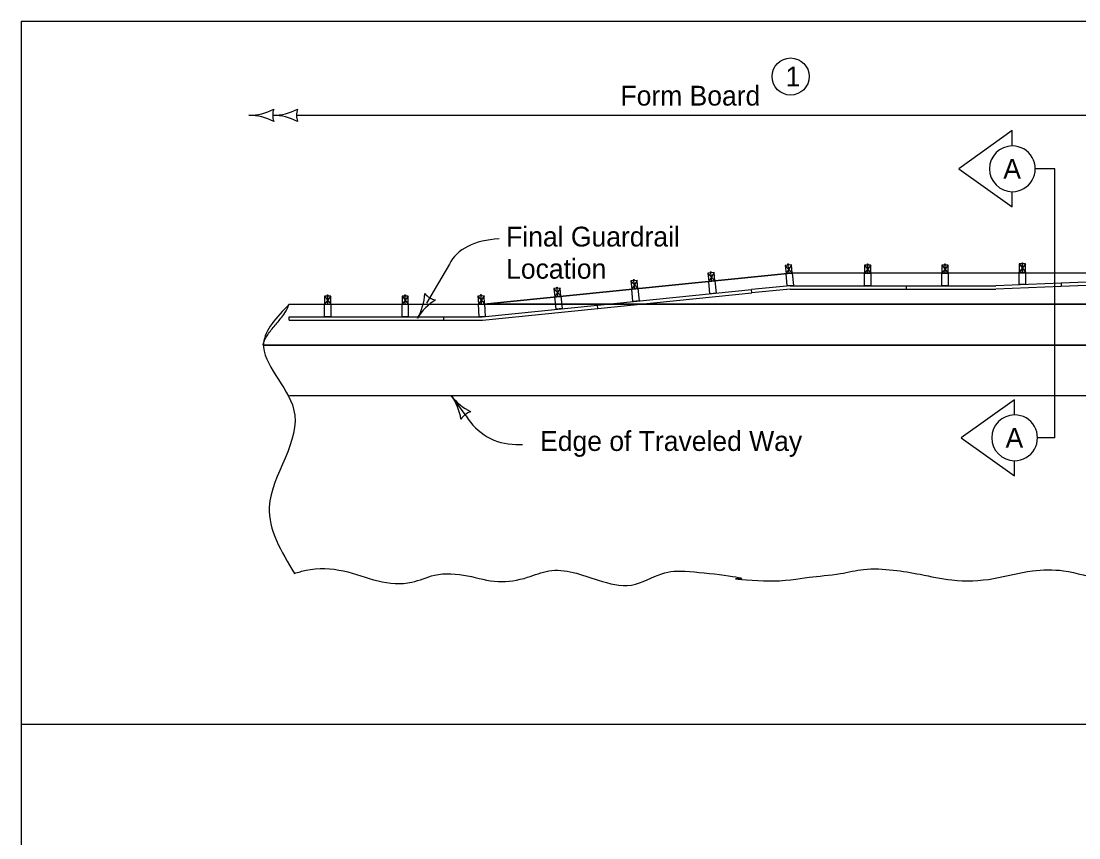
# Model space of a CAD drawing. Extents: x 10133 to 81668, y 7924 to 12229.
# Drawn here: x 10147 to 11002, y 11570 to 12229 of the extents above; entities that cross this region are included whole.
import ezdxf

# ---------------------------------------------------------------- set-up
doc = ezdxf.new("R2010")
doc.units = 0
for name, color, linetype in [('dsnTextFinalPlan', 7, 'Continuous'), ('Level 1', 7, 'Continuous'), ('Level 12', 7, 'Continuous'), ('Level 4', 7, 'Continuous'), ('Level 5', 7, 'Continuous'), ('Level 6', 7, 'Continuous'), ('Level 7', 7, 'Continuous')]:
    doc.layers.add(name, color=color, linetype=linetype)

msp = doc.modelspace()

# ---------------------------------------------------------------- linework, layer by layer
at = {"layer": 'dsnTextFinalPlan'}
for p, q in [((11398.9, 12034.13), (10987.34, 12017.66)), ((10521.34, 12000.48), (10769.12, 12025.56)), ((11016.97, 12025.56), (10769.12, 12025.56)), ((11399.01, 12031.42), (10987.34, 12014.95)), ((10987.34, 12017.66), (10934.57, 12015.55)), ((10987.34, 12017.66), (10987.45, 12014.96)), ((10987.34, 12017.66), (10987.45, 12014.96)), ((10987.45, 12014.96), (10934.6, 12012.84)), ((10363.59, 12000.48), (10521.34, 12000.48)), ((10363.59, 12000.48), (11495.7, 12000.48)), ((10342.6, 11967.5), (11990.07, 11967.5)), ((11495.7, 11967.5), (10342.6, 11967.5)), ((10363.81, 11926.85), (11977.6, 11926.85))]:
    msp.add_line(p, q, dxfattribs=at)
for points in [[(10363.59, 12000.48), (10342.94, 11968.93), (10367.3, 11915.85), (10347.6, 11836.75), (10367.88, 11783.14)], [(10342.6, 11967.5), (10342.94, 11968.93), (10344.63, 11973.01), (10347.04, 11976.93), (10353.1, 11984.54), (10359.25, 11992.23), (10362.78, 11998.34), (10363.59, 12000.48)], [(10367.88, 11783.14), (10377.31, 11785.71), (10407.53, 11785.14), (10435.47, 11777.16), (10462.84, 11776.02), (10481.09, 11781.72), (10507.89, 11781.15), (10532.41, 11776.59), (10556.36, 11780.01), (10573.47, 11785.14), (10613.38, 11777.73), (10640.18, 11773.73), (10664.7, 11782.86), (10687.51, 11784.57), (10726.29, 11778.87), (10725.72, 11778.87), (10746.87, 11777.26), (10783.94, 11780.12), (10809.03, 11782.97), (10827.84, 11786.39), (10851.79, 11785.82), (10873.46, 11782.4), (10899.12, 11777.84), (10932.77, 11778.98), (10964.13, 11785.25), (10989.22, 11785.25), (11021.15, 11777.84), (11050.23, 11774.98), (11083.88, 11781.83), (11116.38, 11785.25), (11150.59, 11778.41), (11176.25, 11775.55), (11198.49, 11778.98), (11226.43, 11794.38), (11236.7, 11796.66), (11261.22, 11798.94), (11291.88, 11799.51), (11312.98, 11799.51), (11366.29, 11790.23)]]:
    msp.add_spline(points, degree=3, dxfattribs=at)
at = {"layer": 'Level 1'}
for q in [(10147.13, 10619.21), (13242.82, 12229.21)]:
    msp.add_line((10147.13, 12229.21), q, dxfattribs=at)
at = {"layer": 'Level 12'}
msp.add_circle((10768.8, 12184.47), 15, dxfattribs=at)
at = {"layer": 'Level 4'}
for p, q in [((10769.41, 12032.39), (10765.1, 12025.26)), ((10766.83, 12033.11), (10766.82, 12033.18)), ((10831.09, 12033.2), (10831.09, 12033.27)), ((10893.59, 12033.2), (10893.59, 12033.27)), ((10953.59, 12033.09), (10958.59, 12026.42)), ((10958.59, 12033.09), (10953.59, 12026.42)), ((10956.09, 12034.06), (10956.09, 12034.13)), ((10956.09, 12026.42), (10956.09, 12033.09)), ((10769.12, 12025.56), (10521.34, 12000.48)), ((10701.98, 12025.61), (10707.62, 12019.48)), ((10706.95, 12026.11), (10702.64, 12018.98)), ((10704.37, 12026.83), (10704.36, 12026.9)), ((10705.13, 12019.23), (10704.46, 12025.86)), ((10764.44, 12031.89), (10770.08, 12025.76)), ((10765.1, 12025.26), (10770.08, 12025.76)), ((10767.59, 12025.51), (10765.1, 12025.26)), ((10767.59, 12025.51), (10765.1, 12025.26)), ((10766.1, 12015.3), (10765.1, 12025.26)), ((10767.59, 12025.51), (10766.93, 12032.14)), ((11020.3, 12025.56), (10769.12, 12025.56)), ((10770.08, 12025.76), (10771.08, 12015.8)), ((10828.59, 12032.23), (10833.59, 12025.56)), ((10833.59, 12032.23), (10828.59, 12025.56)), ((10828.59, 12025.56), (10833.59, 12025.56)), ((10828.59, 12015.55), (10828.59, 12025.56)), ((10831.09, 12025.56), (10831.09, 12032.23)), ((10833.59, 12025.56), (10833.59, 12015.55)), ((10891.09, 12032.23), (10896.09, 12025.56)), ((10896.09, 12032.23), (10891.09, 12025.56)), ((10891.09, 12025.56), (10896.09, 12025.56)), ((10891.09, 12015.55), (10891.09, 12025.56)), ((10893.59, 12025.56), (10893.59, 12032.23)), ((10896.09, 12025.56), (10896.09, 12015.55)), ((10953.59, 12026.42), (10958.59, 12026.42)), ((10953.59, 12016.41), (10953.59, 12026.42)), ((10958.59, 12026.42), (10958.59, 12016.41)), ((10639.79, 12019.36), (10645.43, 12013.23)), ((10644.76, 12019.86), (10640.46, 12012.73)), ((10642.18, 12020.58), (10642.17, 12020.65)), ((10642.94, 12012.98), (10642.28, 12019.61)), ((10702.64, 12018.98), (10707.62, 12019.48)), ((10703.64, 12009.02), (10702.64, 12018.98)), ((10707.62, 12019.48), (10708.62, 12009.52)), ((10768.59, 12015.55), (10737.23, 12012.4)), ((10771.08, 12015.8), (10766.1, 12015.3)), ((10768.59, 12015.55), (10862.34, 12015.55)), ((10833.59, 12015.55), (10828.59, 12015.55)), ((10862.34, 12012.84), (10862.34, 12015.55)), ((10862.34, 12015.55), (10934.57, 12015.55)), ((10862.34, 12012.84), (10862.34, 12015.55)), ((10896.09, 12015.55), (10891.09, 12015.55)), ((10958.59, 12016.41), (10953.59, 12016.41)), ((10392.34, 12007.15), (10397.34, 12000.48)), ((10397.34, 12007.15), (10392.34, 12000.48)), ((10394.84, 12008.12), (10394.84, 12008.19)), ((10394.84, 12000.48), (10394.84, 12007.15)), ((10454.84, 12007.15), (10459.84, 12000.48)), ((10459.84, 12007.15), (10454.84, 12000.48)), ((10457.34, 12008.12), (10457.34, 12008.19)), ((10457.34, 12000.48), (10457.34, 12007.15)), ((10516.23, 12007.21), (10521.56, 12000.77)), ((10521.23, 12007.46), (10516.56, 12000.52)), ((10518.68, 12008.32), (10518.68, 12008.39)), ((10519.06, 12000.65), (10518.73, 12007.34)), ((10577.61, 12013.15), (10583.25, 12006.98)), ((10582.59, 12013.65), (10578.27, 12006.48)), ((10578.27, 12006.48), (10583.25, 12006.99)), ((10580, 12014.37), (10579.99, 12014.44)), ((10580.76, 12006.73), (10580.1, 12013.4)), ((10583.25, 12006.99), (10584.25, 11996.98)), ((10612.85, 11999.9), (10737.23, 12012.4)), ((10613.12, 11997.2), (10737.5, 12009.7)), ((10640.46, 12012.73), (10645.43, 12013.23)), ((10641.46, 12002.77), (10640.46, 12012.73)), ((10645.43, 12013.23), (10646.43, 12003.27)), ((10708.62, 12009.52), (10703.64, 12009.02)), ((10737.5, 12009.7), (10737.23, 12012.4)), ((10737.49, 12009.72), (10737.23, 12012.4)), ((10768.59, 12012.84), (10737.49, 12009.72)), ((10768.59, 12012.84), (10862.34, 12012.84)), ((10862.34, 12012.84), (10934.6, 12012.84)), ((10392.34, 12000.48), (10397.35, 12000.48)), ((10392.34, 11990.48), (10392.34, 12000.48)), ((10397.35, 12000.48), (10397.35, 11990.48)), ((10454.84, 12000.48), (10459.85, 12000.48)), ((10454.84, 11990.48), (10454.84, 12000.48)), ((10459.85, 12000.48), (10459.85, 11990.48)), ((10516.56, 12000.52), (10521.56, 12000.77)), ((10517.06, 11990.48), (10516.56, 12000.52)), ((10519.57, 11990.48), (10612.85, 11999.9)), ((10521.34, 12000.48), (11495.7, 12000.48)), ((11553.25, 12000.48), (10521.34, 12000.48)), ((10521.56, 12000.77), (10522.06, 11990.73)), ((10579.27, 11996.48), (10578.27, 12006.48)), ((10613.12, 11997.19), (10612.85, 11999.9)), ((10613.12, 11997.2), (10612.85, 11999.9)), ((10646.43, 12003.27), (10641.46, 12002.77)), ((10363.59, 11990.48), (10488.59, 11990.48)), ((10363.59, 11987.77), (10363.59, 11990.48)), ((10397.35, 11990.48), (10392.34, 11990.48)), ((10459.85, 11990.48), (10454.84, 11990.48)), ((10488.59, 11990.48), (10519.57, 11990.48)), ((10488.59, 11987.77), (10488.59, 11990.48)), ((10522.06, 11990.73), (10517.06, 11990.48)), ((10519.84, 11987.77), (10613.12, 11997.19)), ((10584.25, 11996.98), (10579.27, 11996.48)), ((10363.59, 11987.77), (10488.59, 11987.77)), ((10488.59, 11987.77), (10519.84, 11987.77)), ((12302.71, 11661.22), (10147.13, 11661.22))]:
    msp.add_line(p, q, dxfattribs=at)
for points in [[(10765.1, 12025.26), (10770.08, 12025.76), (10769.41, 12032.39), (10764.44, 12031.89)], [(10953.59, 12026.42), (10958.59, 12026.42), (10958.59, 12033.09), (10953.59, 12033.09)], [(10702.64, 12018.98), (10707.62, 12019.48), (10706.95, 12026.11), (10701.98, 12025.61)], [(10828.59, 12025.56), (10833.59, 12025.56), (10833.59, 12032.23), (10828.59, 12032.23)], [(10891.09, 12025.56), (10896.09, 12025.56), (10896.09, 12032.23), (10891.09, 12032.23)], [(10640.46, 12012.73), (10645.43, 12013.23), (10644.76, 12019.86), (10639.79, 12019.36)], [(10392.34, 12000.48), (10397.34, 12000.48), (10397.34, 12007.15), (10392.34, 12007.15)], [(10454.84, 12000.48), (10459.84, 12000.48), (10459.84, 12007.15), (10454.84, 12007.15)], [(10516.56, 12000.52), (10521.56, 12000.77), (10521.23, 12007.46), (10516.23, 12007.21)], [(10578.27, 12006.48), (10583.25, 12006.98), (10582.59, 12013.65), (10577.61, 12013.15)]]:
    msp.add_lwpolyline(points, close=True, dxfattribs=at)
for points in [[(10766.6, 12032.11), (10766.55, 12032.54), (10767.22, 12032.6), (10767.26, 12032.18)], [(10766.69, 12032.55), (10766.64, 12033.09), (10767.02, 12033.13), (10767.08, 12032.59)], [(10830.75, 12032.23), (10830.75, 12032.66), (10831.42, 12032.66), (10831.42, 12032.23)], [(10830.89, 12032.66), (10830.89, 12033.2), (10831.28, 12033.2), (10831.28, 12032.66)], [(10893.26, 12032.23), (10893.26, 12032.66), (10893.92, 12032.66), (10893.92, 12032.23)], [(10893.39, 12032.66), (10893.39, 12033.2), (10893.78, 12033.2), (10893.78, 12032.66)], [(10955.76, 12033.09), (10955.76, 12033.52), (10956.42, 12033.52), (10956.42, 12033.09)], [(10955.89, 12033.52), (10955.89, 12034.06), (10956.28, 12034.06), (10956.28, 12033.52)], [(10704.13, 12025.83), (10704.09, 12026.26), (10704.75, 12026.33), (10704.79, 12025.9)], [(10704.23, 12026.27), (10704.17, 12026.81), (10704.56, 12026.85), (10704.61, 12026.31)], [(10641.94, 12019.58), (10641.9, 12020.01), (10642.56, 12020.08), (10642.61, 12019.65)], [(10642.04, 12020.02), (10641.99, 12020.56), (10642.37, 12020.6), (10642.43, 12020.06)], [(10394.51, 12007.15), (10394.51, 12007.58), (10395.18, 12007.58), (10395.18, 12007.15)], [(10394.65, 12007.58), (10394.65, 12008.12), (10395.04, 12008.12), (10395.04, 12007.58)], [(10457.01, 12007.15), (10457.01, 12007.58), (10457.68, 12007.58), (10457.68, 12007.15)], [(10457.15, 12007.58), (10457.15, 12008.12), (10457.54, 12008.12), (10457.54, 12007.58)], [(10518.4, 12007.32), (10518.38, 12007.76), (10519.04, 12007.79), (10519.06, 12007.36)], [(10518.51, 12007.76), (10518.49, 12008.31), (10518.88, 12008.33), (10518.9, 12007.78)], [(10579.77, 12013.37), (10579.72, 12013.8), (10580.39, 12013.87), (10580.43, 12013.44)], [(10579.86, 12013.81), (10579.81, 12014.35), (10580.19, 12014.39), (10580.25, 12013.85)], [(10519.06, 12000.65), (10516.56, 12000.52), (10516.56, 12000.52)]]:
    msp.add_lwpolyline(points, dxfattribs=at)
at = {"layer": 'Level 5'}
msp.add_line((10370.4, 12153.34), (11392.81, 12153.34), dxfattribs=at)
msp.add_line((10370.4, 12153.34), (11392.81, 12153.34), dxfattribs=at)
for centre, radius, start, end in [((10331.18, 12195.69), 42.5, 270, 298.07249), ((10331.18, 12195.69), 42.5, 270, 298.07249), ((10331.18, 12110.69), 42.5, 61.92751, 90), ((10331.18, 12110.69), 42.5, 61.92751, 90), ((10350.4, 12195.69), 42.5, 270, 298.07249), ((10366.82, 12153.19), 16.42, 162.26665, 197.73335), ((10350.4, 12195.69), 42.5, 270, 298.07249), ((10366.82, 12153.19), 16.42, 162.26665, 197.73335), ((10350.4, 12110.69), 42.5, 61.92751, 90), ((10350.4, 12110.69), 42.5, 61.92751, 90), ((10386.04, 12153.19), 16.42, 162.26665, 197.73335), ((10386.04, 12153.19), 16.42, 162.26665, 197.73335)]:
    msp.add_arc(centre, radius, start, end, dxfattribs=at)
at = {"layer": 'Level 6'}
for p, q in [((10493.11, 12032.86), (10474.56, 12001.51)), ((10493.11, 12032.86), (10474.56, 12001.51)), ((10506.72, 11910.41), (10494.61, 11926.85)), ((10506.72, 11910.41), (10494.61, 11926.85)), ((10546.81, 11887.34), (10552.25, 11887.34)), ((10546.81, 11887.34), (10552.25, 11887.34))]:
    msp.add_line(p, q, dxfattribs=at)
for centre, radius, start, end in [((10430.79, 12011.01), 42.5, 329.37973, 357.45222), ((10430.79, 12011.01), 42.5, 329.37973, 357.45222), ((10485.52, 12020.03), 16.42, 221.64638, 257.11308), ((10485.52, 12020.03), 16.42, 221.64638, 257.11308), ((10503.94, 11967.72), 42.5, 121.30724, 149.37973), ((10503.94, 11967.72), 42.5, 121.30724, 149.37973), ((10528.83, 11952.06), 42.5, 216.37256, 244.44505), ((10460.39, 11901.65), 42.5, 8.30007, 36.37256), ((10528.83, 11952.06), 42.5, 216.37256, 244.44505), ((10460.39, 11901.65), 42.5, 8.30007, 36.37256), ((10515.74, 11898.16), 16.42, 108.63921, 144.10591), ((10515.74, 11898.16), 16.42, 108.63921, 144.10591), ((10546.86, 11933.79), 46.46, 210.22743, 270), ((10546.86, 11933.79), 46.46, 210.22743, 270)]:
    msp.add_arc(centre, radius, start, end, dxfattribs=at)
msp.add_ellipse((10574.2, 11993.81), major_axis=(-81.09, 39.04), ratio=0.555556, start_param=5.482641, end_param=6.283185, dxfattribs=at)
msp.add_ellipse((10574.2, 11993.81), major_axis=(-81.09, 39.04), ratio=0.555556, start_param=5.482641, end_param=6.283185, dxfattribs=at)
at = {"layer": 'Level 7'}
for p, q in [((10982.21, 12109.95), (10966.44, 12109.95)), ((10982.21, 12109.95), (10966.44, 12109.95)), ((10982.21, 11892.67), (10982.21, 12109.95)), ((10982.21, 11892.67), (10982.21, 12109.95)), ((10982.21, 11892.67), (10968.26, 11892.67)), ((10982.21, 11892.67), (10968.26, 11892.67))]:
    msp.add_line(p, q, dxfattribs=at)
for points in [[(10947.95, 12128.44), (10947.95, 12140.76), (10904.82, 12109.95), (10947.95, 12079.14), (10947.95, 12091.46)], [(10949.77, 11911.15), (10949.77, 11923.47), (10906.64, 11892.66), (10949.77, 11861.85), (10949.77, 11874.18)]]:
    msp.add_lwpolyline(points, dxfattribs=at)
for centre, start, end in [((10947.95, 12109.95), 90.00083, 269.99917), ((10947.95, 12109.95), 269.99917, 90.00083), ((10949.77, 11892.67), 90.00083, 269.99917), ((10949.77, 11892.67), 269.99917, 90.00083)]:
    msp.add_arc(centre, 18.49, start, end, dxfattribs=at)

# ---------------------------------------------------------------- texts
at = {"layer": 'Level 12'}
msp.add_text('1', height=16, dxfattribs=at).set_placement((10764.72, 12176.47))
at = {"layer": 'Level 5'}
msp.add_text('Form Board', height=16, dxfattribs=at).set_placement((10631.35, 12161.03))
msp.add_text('Form Board', height=16, dxfattribs=at).set_placement((10631.35, 12161.03))
at = {"layer": 'Level 6'}
for s, p in [('Final Guardrail ', (10539, 12047.19)), ('Final Guardrail ', (10539, 12047.19)), ('Location', (10539, 12021.19)), ('Location', (10539, 12021.19)), ('Edge of Traveled Way', (10566.45, 11882.06)), ('Edge of Traveled Way', (10566.45, 11882.06))]:
    msp.add_text(s, height=16, dxfattribs=at).set_placement(p)
at = {"layer": 'Level 7'}
for p in [(10940.67, 12101.95), (10942.49, 11884.66)]:
    msp.add_text('A', height=16, dxfattribs=at).set_placement(p)

doc.saveas('drawing.dxf')
